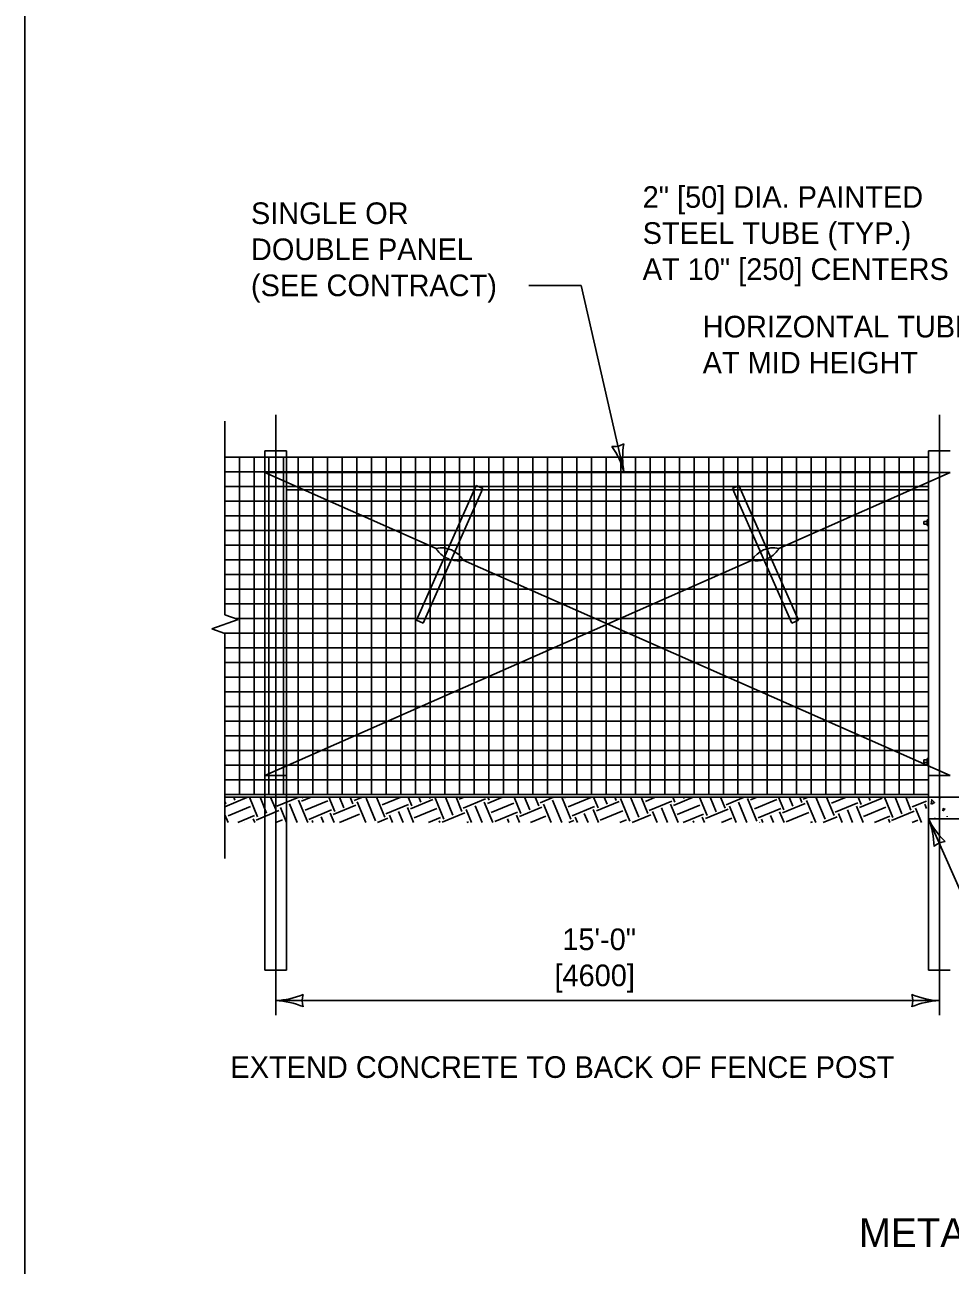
# Model space of a CAD drawing. Extents: x 49991.4 to 50021, y 49987.6 to 50011.4.
# Drawn here: x 49999.384 to 50001.949, y 49992.12 to 49995.56 of the extents above; entities that cross this region are included whole.
import ezdxf

# ---------------------------------------------------------------- set-up
doc = ezdxf.new("R2010")
doc.units = 0
for name, color, linetype in [('Level 1', 7, 'Continuous'), ('Level 2', 7, 'Continuous'), ('Level 3', 7, 'Continuous'), ('Level 4', 7, 'Continuous'), ('Level 5', 7, 'Continuous'), ('Level 6', 7, 'Continuous')]:
    doc.layers.add(name, color=color, linetype=linetype)

msp = doc.modelspace()

# ---------------------------------------------------------------- linework, layer by layer
at = {"layer": 'Level 1'}
for p, q in [((50000.1092, 49994.3778), (50000.0492, 49994.3778)), ((50000.0492, 49994.3778), (50000.0492, 49993.4177)), ((50000.1092, 49993.4177), (50000.1092, 49994.3778)), ((50001.9492, 49994.3778), (50001.8892, 49994.3778)), ((50001.8892, 49994.3778), (50001.8892, 49993.3577)), ((50001.8892, 49994.3604), (49999.9385, 49994.3604)), ((49999.9791, 49993.4257), (49999.9791, 49994.3604)), ((50000.0197, 49993.4257), (50000.0197, 49994.3604)), ((50000.0604, 49993.4257), (50000.0604, 49994.3604)), ((50000.101, 49993.4257), (50000.101, 49994.3604)), ((50000.1416, 49993.4257), (50000.1416, 49994.3604)), ((50000.1823, 49993.4257), (50000.1823, 49994.3604)), ((50000.2229, 49993.4257), (50000.2229, 49994.3604)), ((50000.2636, 49993.4257), (50000.2636, 49994.3604)), ((50000.3042, 49993.4257), (50000.3042, 49994.3604)), ((50000.3448, 49993.4257), (50000.3448, 49994.3604)), ((50000.3855, 49993.4257), (50000.3855, 49994.3604)), ((50000.4261, 49993.4257), (50000.4261, 49994.3604)), ((50000.4668, 49993.4257), (50000.4668, 49994.3604)), ((50000.5074, 49993.4257), (50000.5074, 49994.3604)), ((50000.5481, 49993.4257), (50000.5481, 49994.3604)), ((50000.5887, 49993.4257), (50000.5887, 49994.3604)), ((50000.6293, 49993.4257), (50000.6293, 49994.3604)), ((50000.67, 49993.4257), (50000.67, 49994.3604)), ((50000.7106, 49993.4257), (50000.7106, 49994.3604)), ((50000.7513, 49993.4257), (50000.7513, 49994.3604)), ((50000.7919, 49993.4257), (50000.7919, 49994.3604)), ((50000.8326, 49993.4257), (50000.8326, 49994.3604)), ((50000.8732, 49993.4257), (50000.8732, 49994.3604)), ((50000.9138, 49993.4257), (50000.9138, 49994.3604)), ((50000.9545, 49993.4257), (50000.9545, 49994.3604)), ((50000.9951, 49993.4257), (50000.9951, 49994.3604)), ((50001.0358, 49993.4257), (50001.0358, 49994.3604)), ((50001.0764, 49993.4257), (50001.0764, 49994.3604)), ((50001.117, 49993.4257), (50001.117, 49994.3604)), ((50001.1577, 49993.4257), (50001.1577, 49994.3604)), ((50001.1983, 49993.4257), (50001.1983, 49994.3604)), ((50001.239, 49993.4257), (50001.239, 49994.3604)), ((50001.2796, 49993.4257), (50001.2796, 49994.3604)), ((50001.3203, 49993.4257), (50001.3203, 49994.3604)), ((50001.3609, 49993.4257), (50001.3609, 49994.3604)), ((50001.4015, 49993.4257), (50001.4015, 49994.3604)), ((50001.4422, 49993.4257), (50001.4422, 49994.3604)), ((50001.4828, 49993.4257), (50001.4828, 49994.3604)), ((50001.5235, 49993.4257), (50001.5235, 49994.3604)), ((50001.5641, 49993.4257), (50001.5641, 49994.3604)), ((50001.6047, 49993.4257), (50001.6047, 49994.3604)), ((50001.6454, 49993.4257), (50001.6454, 49994.3604)), ((50001.686, 49993.4257), (50001.686, 49994.3604)), ((50001.7267, 49993.4257), (50001.7267, 49994.3604)), ((50001.7673, 49993.4257), (50001.7673, 49994.3604)), ((50001.808, 49993.4257), (50001.808, 49994.3604)), ((50001.8486, 49993.4257), (50001.8486, 49994.3604)), ((50001.8892, 49994.3198), (49999.9385, 49994.3198)), ((50000.0492, 49994.3177), (50001.9492, 49994.3177)), ((50000.0492, 49994.3177), (50000.5241, 49994.1077)), ((50001.4742, 49994.1077), (50001.9492, 49994.3177)), ((50001.8892, 49994.2792), (49999.9385, 49994.2792)), ((50000.1092, 49994.2698), (50001.8892, 49994.2698)), ((50000.4696, 49993.9085), (50000.6347, 49994.2821)), ((50000.653, 49994.274), (50000.4879, 49993.9005)), ((50000.6347, 49994.2821), (50000.653, 49994.274)), ((50001.3636, 49994.2821), (50001.3453, 49994.274)), ((50001.3453, 49994.274), (50001.5104, 49993.9005)), ((50001.5287, 49993.9086), (50001.3636, 49994.2821)), ((50001.8892, 49994.2385), (49999.9385, 49994.2385)), ((50001.8892, 49994.1979), (49999.9385, 49994.1979)), ((50001.8759, 49994.1752), (50001.8759, 49994.1827)), ((50001.8892, 49994.1827), (50001.8759, 49994.1827)), ((50001.8892, 49994.1752), (50001.8759, 49994.1752)), ((50001.8857, 49994.1866), (50001.8857, 49994.1711)), ((50001.8892, 49994.1866), (50001.8857, 49994.1866)), ((50001.8857, 49994.1711), (50001.8892, 49994.1711)), ((50001.8892, 49994.1572), (49999.9385, 49994.1572)), ((50001.8892, 49994.1166), (49999.9385, 49994.1166)), ((50001.8892, 49994.0759), (49999.9385, 49994.0759)), ((50001.3999, 49994.0748), (50000.0492, 49993.4777)), ((50000.5985, 49994.0749), (50001.9492, 49993.4777)), ((50001.8892, 49994.0353), (49999.9385, 49994.0353)), ((50001.8892, 49993.9947), (49999.9385, 49993.9947)), ((50001.8892, 49993.954), (49999.9385, 49993.954)), ((50001.8892, 49993.9134), (49999.9677, 49993.9134)), ((50000.4696, 49993.9085), (50000.4879, 49993.9005)), ((50001.5287, 49993.9086), (50001.5104, 49993.9005)), ((50001.8892, 49993.8728), (49999.9359, 49993.8728)), ((50001.8892, 49993.8321), (49999.9385, 49993.8321)), ((50001.8892, 49993.7915), (49999.9385, 49993.7915)), ((50001.8892, 49993.7508), (49999.9385, 49993.7508)), ((50001.8892, 49993.7102), (49999.9385, 49993.7102)), ((50001.8892, 49993.6695), (49999.9385, 49993.6695)), ((50001.8892, 49993.6289), (49999.9385, 49993.6289)), ((50001.8892, 49993.5882), (49999.9385, 49993.5882)), ((50001.8892, 49993.5476), (49999.9385, 49993.5476)), ((50001.8759, 49993.5136), (50001.8759, 49993.5211)), ((50001.8892, 49993.5211), (50001.8759, 49993.5211)), ((50001.8892, 49993.5136), (50001.8759, 49993.5136)), ((50001.8892, 49993.507), (49999.9385, 49993.507)), ((50000.0492, 49993.4777), (50000.1092, 49993.4777)), ((50001.9492, 49993.4777), (50001.8892, 49993.4777)), ((50001.8892, 49993.4663), (49999.9385, 49993.4663)), ((50001.8892, 49993.4257), (49999.9385, 49993.4257)), ((49999.9385, 49993.4177), (50005.4753, 49993.4177)), ((49999.9385, 49993.3915), (49999.9994, 49993.4167)), ((49999.9628, 49993.4177), (49999.9661, 49993.4098)), ((50000.0063, 49993.4177), (50000.029, 49993.363)), ((50000.0356, 49993.4177), (50000.054, 49993.3733)), ((50000.065, 49993.4177), (50000.0791, 49993.3837)), ((50000.0724, 49993.4176), (50000.0727, 49993.4177)), ((50000.0827, 49993.3926), (50000.1435, 49993.4177)), ((50000.1422, 49993.4098), (50000.1679, 49993.3476)), ((50000.1504, 49993.4064), (50000.1777, 49993.4177)), ((50000.153, 49993.4177), (50000.1542, 49993.4148)), ((50000.1607, 49993.3814), (50000.2234, 49993.4073)), ((50000.2269, 49993.4177), (50000.2432, 49993.3783)), ((50000.2563, 49993.4177), (50000.2683, 49993.3887)), ((50000.2856, 49993.4177), (50000.2933, 49993.3991)), ((50000.2964, 49993.4082), (50000.3194, 49993.4177)), ((50000.3303, 49993.4149), (50000.3562, 49993.3523)), ((50000.3584, 49993.4177), (50000.3813, 49993.3627)), ((50000.3746, 49993.3966), (50000.4257, 49993.4177)), ((50000.4465, 49993.4177), (50000.4564, 49993.3938)), ((50000.4526, 49993.3854), (50000.5152, 49993.4113)), ((50000.4758, 49993.4177), (50000.4815, 49993.4042)), ((50000.5052, 49993.4177), (50000.5065, 49993.4145)), ((50000.5204, 49993.4177), (50000.5454, 49993.3573)), ((50000.5497, 49993.4177), (50000.5705, 49993.3677)), ((50000.5791, 49993.4177), (50000.5955, 49993.378)), ((50000.5882, 49993.4122), (50000.6016, 49993.4177)), ((50000.5986, 49993.3871), (50000.6612, 49993.4131)), ((50000.6664, 49993.4006), (50000.7078, 49993.4177)), ((50000.6671, 49993.4177), (50000.6707, 49993.4092)), ((50000.74, 49993.4177), (50000.7586, 49993.3727)), ((50000.7693, 49993.4177), (50000.7837, 49993.3831)), ((50000.7987, 49993.4177), (50000.8087, 49993.3935)), ((50000.8124, 49993.4023), (50000.8495, 49993.4177)), ((50000.8467, 49993.4092), (50000.8723, 49993.3476)), ((50000.8726, 49993.4177), (50000.8977, 49993.357)), ((50000.88, 49993.4162), (50000.8837, 49993.4177)), ((50000.8904, 49993.3911), (50000.953, 49993.4171)), ((50000.9606, 49993.4177), (50000.9729, 49993.3881)), ((50000.99, 49993.4177), (50000.9979, 49993.3985)), ((50001.0193, 49993.4177), (50001.023, 49993.4089)), ((50001.0349, 49993.4143), (50001.0608, 49993.3517)), ((50001.0628, 49993.4177), (50001.0858, 49993.3621)), ((50001.0921, 49993.4177), (50001.1109, 49993.3724)), ((50001.1042, 49993.4063), (50001.1317, 49993.4177)), ((50001.1146, 49993.3813), (50001.1772, 49993.4072)), ((50001.1802, 49993.4177), (50001.186, 49993.4036)), ((50001.1822, 49993.3951), (50001.2367, 49993.4177)), ((50001.2095, 49993.4177), (50001.2111, 49993.4139)), ((50001.2541, 49993.4177), (50001.2751, 49993.3671)), ((50001.2834, 49993.4177), (50001.3001, 49993.3774)), ((50001.3128, 49993.4177), (50001.3252, 49993.3878)), ((50001.3282, 49993.3969), (50001.3784, 49993.4177)), ((50001.3871, 49993.414), (50001.4131, 49993.3514)), ((50001.396, 49993.4103), (50001.4139, 49993.4177)), ((50001.4064, 49993.3853), (50001.469, 49993.4112)), ((50001.4736, 49993.4177), (50001.4882, 49993.3825)), ((50001.503, 49993.4177), (50001.5133, 49993.3929)), ((50001.5323, 49993.4177), (50001.5383, 49993.4033)), ((50001.542, 49993.4121), (50001.5556, 49993.4177)), ((50001.5513, 49993.4086), (50001.5766, 49993.3476)), ((50001.5769, 49993.4177), (50001.6023, 49993.3564)), ((50001.6062, 49993.4177), (50001.6274, 49993.3668)), ((50001.62, 49993.4009), (50001.6606, 49993.4177)), ((50001.6943, 49993.4177), (50001.7025, 49993.3979)), ((50001.6982, 49993.3893), (50001.7608, 49993.4152)), ((50001.7236, 49993.4177), (50001.7276, 49993.4083)), ((50001.7671, 49993.4177), (50001.7904, 49993.3615)), ((50001.7965, 49993.4177), (50001.8155, 49993.3718)), ((50001.8258, 49993.4177), (50001.8405, 49993.3822)), ((50001.8338, 49993.4161), (50001.8377, 49993.4177)), ((50001.8442, 49993.3911), (50001.8832, 49993.4072)), ((50001.9217, 49993.4149), (50001.9217, 49993.4171)), ((49999.9385, 49993.4056), (49999.941, 49993.3994)), ((49999.9471, 49993.3657), (50000.0097, 49993.3917)), ((50000.0251, 49993.3545), (50000.0877, 49993.3805)), ((50000.0921, 49993.3891), (50000.1093, 49993.3476)), ((50000.1171, 49993.3995), (50000.1386, 49993.3476)), ((50000.1711, 49993.3563), (50000.2337, 49993.3823)), ((50000.2301, 49993.3734), (50000.2408, 49993.3476)), ((50000.2389, 49993.3697), (50000.3016, 49993.3957)), ((50000.3052, 49993.4045), (50000.3288, 49993.3476)), ((50000.3849, 49993.3715), (50000.4476, 49993.3975)), ((50000.4193, 49993.3784), (50000.4321, 49993.3476)), ((50000.4443, 49993.3888), (50000.4614, 49993.3476)), ((50000.4629, 49993.3603), (50000.5256, 49993.3863)), ((50000.5411, 49993.3487), (50000.6037, 49993.3746)), ((50000.6074, 49993.3835), (50000.6223, 49993.3476)), ((50000.6325, 49993.3939), (50000.6516, 49993.3476)), ((50000.6575, 49993.4042), (50000.681, 49993.3476)), ((50000.6767, 49993.3755), (50000.7394, 49993.4015)), ((50000.6871, 49993.3505), (50000.7497, 49993.3764)), ((50000.7547, 49993.3643), (50000.8174, 49993.3903)), ((50000.8217, 49993.3989), (50000.8429, 49993.3476)), ((50000.9007, 49993.3661), (50000.9634, 49993.392)), ((50000.9347, 49993.3728), (50000.9451, 49993.3476)), ((50000.9597, 49993.3832), (50000.9745, 49993.3476)), ((50000.9686, 49993.3795), (50001.0312, 49993.4054)), ((50000.9789, 49993.3545), (50001.0416, 49993.3804)), ((50001.1239, 49993.3778), (50001.1364, 49993.3476)), ((50001.1489, 49993.3882), (50001.1658, 49993.3476)), ((50001.174, 49993.3986), (50001.1951, 49993.3476)), ((50001.1926, 49993.3701), (50001.2552, 49993.396)), ((50001.2708, 49993.3585), (50001.3334, 49993.3844)), ((50001.337, 49993.3933), (50001.356, 49993.3476)), ((50001.3621, 49993.4036), (50001.3853, 49993.3476)), ((50001.4168, 49993.3602), (50001.4794, 49993.3862)), ((50001.4762, 49993.3775), (50001.4886, 49993.3476)), ((50001.4844, 49993.3741), (50001.547, 49993.4)), ((50001.4948, 49993.349), (50001.5574, 49993.375)), ((50001.6304, 49993.3759), (50001.693, 49993.4018)), ((50001.6643, 49993.3826), (50001.6788, 49993.3476)), ((50001.6893, 49993.393), (50001.7081, 49993.3476)), ((50001.7086, 49993.3642), (50001.7712, 49993.3902)), ((50001.7866, 49993.353), (50001.8492, 49993.379)), ((50001.8535, 49993.3876), (50001.8701, 49993.3476)), ((50001.8786, 49993.398), (50001.8832, 49993.3868)), ((49999.9385, 49993.3689), (49999.9473, 49993.3476)), ((49999.9741, 49993.3476), (50000.0201, 49993.3666)), ((49999.9919, 49993.3476), (49999.9919, 49993.3476)), ((50000.0169, 49993.358), (50000.0212, 49993.3476)), ((50000.0791, 49993.3476), (50000.0981, 49993.3554)), ((50000.18, 49993.3527), (50000.1821, 49993.3476)), ((50000.205, 49993.363), (50000.2114, 49993.3476)), ((50000.2563, 49993.3476), (50000.3119, 49993.3706)), ((50000.3613, 49993.3476), (50000.3899, 49993.3594)), ((50000.3942, 49993.368), (50000.4027, 49993.3476)), ((50000.503, 49993.3476), (50000.5359, 49993.3612)), ((50000.5323, 49993.3524), (50000.5342, 49993.3476)), ((50000.6093, 49993.3476), (50000.6141, 49993.3496)), ((50000.7215, 49993.3574), (50000.7255, 49993.3476)), ((50000.7465, 49993.3677), (50000.7549, 49993.3476)), ((50000.7852, 49993.3476), (50000.8277, 49993.3652)), ((50000.8915, 49993.3476), (50000.9059, 49993.3536)), ((50000.9096, 49993.3624), (50000.9158, 49993.3476)), ((50001.0332, 49993.3476), (50001.0519, 49993.3554)), ((50001.0673, 49993.3476), (50001.1196, 49993.3692)), ((50001.209, 49993.3476), (50001.2656, 49993.371)), ((50001.2368, 49993.3518), (50001.2386, 49993.3476)), ((50001.2619, 49993.3621), (50001.2679, 49993.3476)), ((50001.3153, 49993.3476), (50001.3438, 49993.3594)), ((50001.4204, 49993.3476), (50001.4218, 49993.3482)), ((50001.4261, 49993.3568), (50001.4299, 49993.3476)), ((50001.4511, 49993.3671), (50001.4592, 49993.3476)), ((50001.5621, 49993.3476), (50001.5678, 49993.3499)), ((50001.5975, 49993.3476), (50001.6356, 49993.3633)), ((50001.6392, 49993.3722), (50001.6494, 49993.3476)), ((50001.7392, 49993.3476), (50001.7816, 49993.3651)), ((50001.7784, 49993.3565), (50001.782, 49993.3476)), ((50001.8442, 49993.3476), (50001.8596, 49993.3539)), ((50001.8892, 49993.3577), (50003.5733, 49993.3577)), ((50001.9069, 49993.3589), (50001.907, 49993.361)), ((50001.9407, 49993.3633), (50001.9408, 49993.3654))]:
    msp.add_line(p, q, dxfattribs=at)
for points in [[(49999.3835, 49998.9992), (50016.7501, 49998.9992), (50016.7501, 49987.7988), (49999.3835, 49987.7988)], [(50001.8857, 49993.5249), (50001.8857, 49993.5095), (50001.8892, 49993.5095), (50001.8892, 49993.5249)]]:
    msp.add_lwpolyline(points, close=True, dxfattribs=at)
for points in [[(50001.8969, 49993.3984), (50001.8981, 49993.4108), (50001.9062, 49993.4031), (50001.8971, 49993.3984)], [(50001.9291, 49993.3802), (50001.9294, 49993.3862), (50001.9347, 49993.3848), (50001.9291, 49993.3802)]]:
    msp.add_lwpolyline(points, dxfattribs=at)
for centre, start, end in [((50000.5386, 49994.0399), 30.2873, 102.0137), ((50000.584, 49994.1427), 210.2873, 237.8611), ((50001.4598, 49994.0399), 77.9863, 149.7191), ((50001.4143, 49994.1427), 302.1296, 329.7127), ((50000.584, 49994.1427), 254.439, 282.0137), ((50001.4143, 49994.1427), 257.9909, 285.561)]:
    msp.add_arc(centre, 0.0694, start, end, dxfattribs=at)
at = {"layer": 'Level 3'}
for p, q in [((50000.781, 49994.8371), (50000.9264, 49994.8371)), ((50001.0447, 49994.3198), (50000.9264, 49994.8371)), ((50001.8892, 49993.3577), (50002.1928, 49992.6694)), ((50000.0792, 49992.8537), (50001.9192, 49992.8537))]:
    msp.add_line(p, q, dxfattribs=at)
for centre, radius, start, end in [((50001.0161, 49994.4448), 0.0548, 265.0222, 300.7446), ((50000.8204, 49994.2567), 0.233, 15.7107, 34.9605), ((50001.2633, 49994.3604), 0.2223, 170.3394, 190.5229), ((50001.6823, 49993.2765), 0.2223, 1.2527, 21.4362), ((50002.0975, 49993.4621), 0.233, 206.624, 225.8739), ((50001.941, 49993.2404), 0.0548, 95.9355, 131.6579), ((50000.0677, 49993.0864), 0.233, 272.8273, 292.0772), ((50000.2074, 49992.8537), 0.0548, 162.1388, 197.8612), ((50001.9284, 49993.0758), 0.2223, 247.456, 267.6395), ((50001.791, 49992.8537), 0.0548, 342.1388, 17.8612), ((50000.07, 49992.6316), 0.2223, 67.456, 87.6395), ((50001.9307, 49992.621), 0.233, 92.8273, 112.0772)]:
    msp.add_arc(centre, radius, start, end, dxfattribs=at)
at = {"layer": 'Level 4'}
for p, q in [((50000.0492, 49993.4177), (50000.0492, 49992.9377)), ((50000.1092, 49992.9377), (50000.1092, 49993.4177)), ((50001.8892, 49993.3577), (50001.8892, 49992.9377)), ((50000.0492, 49992.9377), (50000.1092, 49992.9377)), ((50001.8892, 49992.9377), (50001.9492, 49992.9377))]:
    msp.add_line(p, q, dxfattribs=at)
for centre, start, end in [((50000.584, 49994.1427), 237.8621, 254.439), ((50001.4143, 49994.1427), 285.5603, 302.1371)]:
    msp.add_arc(centre, 0.0694, start, end, dxfattribs=at)
at = {"layer": 'Level 5'}
for p, q in [((50000.0792, 49992.8137), (50000.0792, 49994.4778)), ((50001.9192, 49992.8137), (50001.9192, 49994.4778))]:
    msp.add_line(p, q, dxfattribs=at)
at = {"layer": 'Level 6'}
for p, q in [((49999.9385, 49994.4604), (49999.9385, 49993.9237)), ((49999.975, 49993.9108), (49999.9385, 49993.9237)), ((49999.975, 49993.9108), (49999.9019, 49993.8849)), ((49999.9385, 49993.8719), (49999.9019, 49993.8849)), ((49999.9385, 49993.8719), (49999.9385, 49993.2475))]:
    msp.add_line(p, q, dxfattribs=at)

# ---------------------------------------------------------------- texts
at = {"layer": 'Level 2'}
for s, height, p in [('2" [50] DIA. PAINTED', 0.060003, (50001.0965, 49995.0521)), ('SINGLE OR ', 0.06, (50000.0105, 49995.0071)), ('STEEL TUBE (TYP.)', 0.060003, (50001.0965, 49994.9521)), ('DOUBLE PANEL', 0.06, (50000.0105, 49994.9071)), ('AT 10" [250] CENTERS', 0.060003, (50001.0965, 49994.8521)), ('(SEE CONTRACT)', 0.06, (50000.0105, 49994.8071)), ('HORIZONTAL TUBES', 0.06, (50001.2629, 49994.6927)), ('AT MID HEIGHT', 0.06, (50001.2629, 49994.5927)), ('15\'-0"', 0.06, (50000.8738, 49992.9937)), ('[4600]', 0.06, (50000.852, 49992.8937)), ('EXTEND CONCRETE TO BACK OF FENCE POST', 0.060003, (49999.9536, 49992.6394)), ('METAL MAINTENANCE ACCESS GATE', 0.08, (50001.696, 49992.1701))]:
    msp.add_text(s, height=height, dxfattribs=at).set_placement(p)

doc.saveas('drawing.dxf')
